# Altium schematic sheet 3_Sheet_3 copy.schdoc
size 302 x 215 mm; Name: A_A4; Symbol: A_A4; Device: A_A4; @Project Name: Quectel_EC200U_Board; REV: 1.1; Date: 11-07-24; Sheet: 1/1; Draw By: Anusha; Company: FervidSmart Solutions; Convert to PCB: yes; Add into BOM: yes; @Page No: 3; @Page Count: 3; @Schematic Name: Quectel_EC200U with BuckBoost Board; @Board Name: Quectel_EC200U with BuckBoost Board; @Update Date: 2025-06-23; @Create Time: 12:09:23; @Update Time: 12:51:10; @Page Name: Sheet_3 copy; @Create Date: 2025-06-19
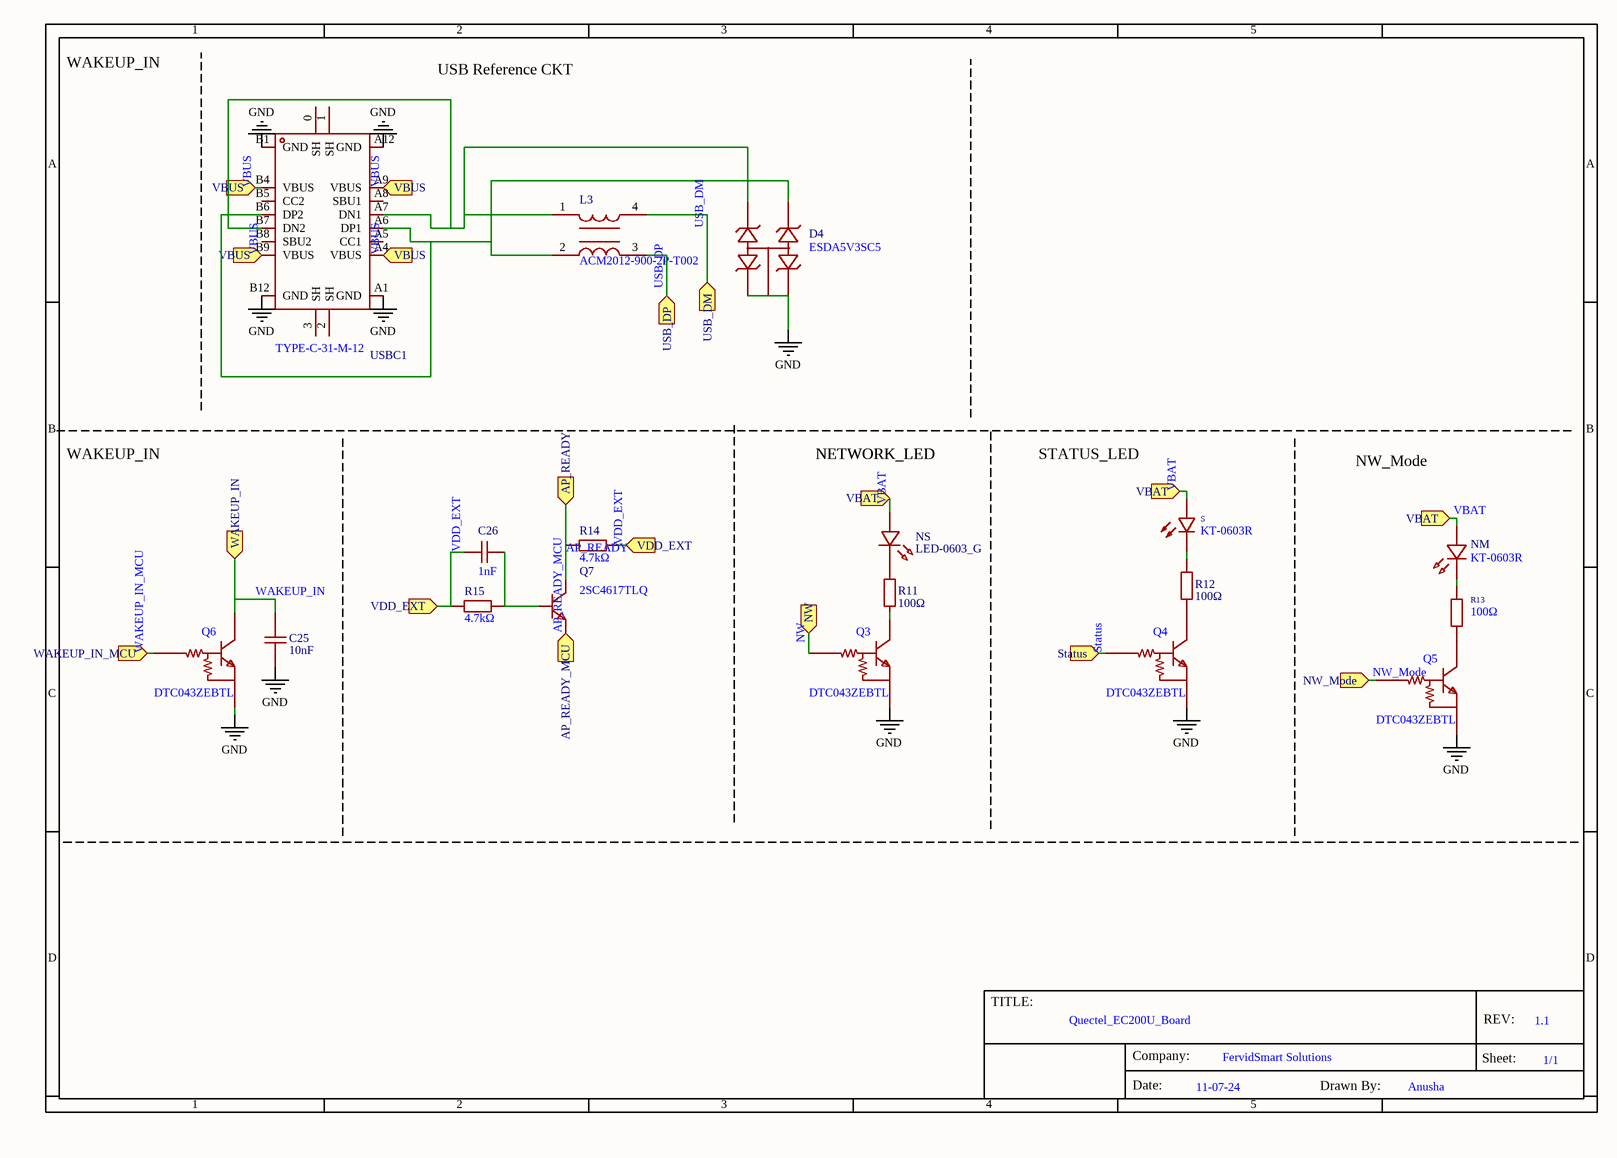
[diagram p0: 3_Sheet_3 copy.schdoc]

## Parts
C25  10nF  [C0603]
C26  1nF  [C0402]
D4  ESDA5V3SC5  [SOT-23-5_L3.0-W1.7-P0.95-LS2.8-BR]
L3  ACM2012-900-2P-T002  [IND-SMD_4P-L2.0-W1.2-TL]
NM  KT-0603R  [LED0603-RD]
NS  LED-0603_G  [LED0603_GREEN]
Q3  DTC043ZEBTL  [SOT-416_L1.6-W0.8-P1.00-LS1.6-BR]
Q4  DTC043ZEBTL  [SOT-416_L1.6-W0.8-P1.00-LS1.6-BR]
Q5  DTC043ZEBTL  [SOT-416_L1.6-W0.8-P1.00-LS1.6-BR]
Q6  DTC043ZEBTL  [SOT-416_L1.6-W0.8-P1.00-LS1.6-BR]
Q7  2SC4617TLQ  [SOT-416F_L1.6-W0.8-P1.00-LS1.6-TR]
R11  100Ω  [R0603]
R12  100Ω  [R0603]
R13  100Ω  [R0603]
R14  4.7kΩ  [R0402]
R15  4.7kΩ  [R0402]
S  KT-0603R  [LED0603-RD]
USBC1  TYPE-C-31-M-12  [USB-C_SMD-TYPE-C-31-M-12]

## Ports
AP_READY (in), AP_READY_MCU (in), NW (in), NW_Mode (in), Status (in), USB_DM (in), USB_DP (in), VBAT (in), VBUS (in), VDD_EXT (in), WAKEUP_IN (in), WAKEUP_IN_MCU (in)

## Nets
GND: C25.1 D4.1 D4.2 D4.3 Q3.2(E) Q4.2(E) Q5.2(E) Q6.2(E) USBC1.A1(GND) USBC1.A12(GND) USBC1.B1(GND) USBC1.B12(GND)
AP_READY: Q7.3(C) R14.1 ; port AP_READY
AP_READY_MCU: Q7.1(E) ; port AP_READY_MCU
NW: Q3.1(B) ; port NW
NW_Mode: Q5.1(B) ; port NW_Mode
Status: Q4.1(B) ; port Status
USB_DM: L3.4 ; port USB_DM
USB_DP: L3.3 ; port USB_DP
VBAT: NM.2(A) NS.1 S.2(+) ; port VBAT
VBUS: USBC1.A4(VBUS) USBC1.A9(VBUS) USBC1.B4(VBUS) USBC1.B9(VBUS) ; port VBUS
VDD_EXT: C26.1 R14.2 R15.1 ; port VDD_EXT
WAKEUP_IN: C25.2 Q6.3(C) ; port WAKEUP_IN
WAKEUP_IN_MCU: Q6.1(B) ; port WAKEUP_IN_MCU
NetC26_2: C26.2 Q7.2(B) R15.2
NetD4_4: D4.4 L3.2 USBC1.A6(DP1) USBC1.B6(DP2)
NetD4_5: D4.5 L3.1 USBC1.A7(DN1) USBC1.B7(DN2)
NetNM_1: NM.1(K) R13.2
NetNS_2: NS.2 R11.1
NetQ3_3: Q3.3(C) R11.2
NetQ4_3: Q4.3(C) R12.2
NetQ5_3: Q5.3(C) R13.1
NetR12_1: R12.1 S.1(-)

Not connected (* = marked no-connect by the designer): USBC1 0(SH) 1(SH) 2(SH) 3(SH) A5(CC1) A8(SBU1) B5(CC2) B8(SBU2)

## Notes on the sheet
- WAKEUP_IN
- USB Reference CKT
- NETWORK_LED
- STATUS_LED
- NW_Mode

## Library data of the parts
C25 = 0603B103K500NT: Manufacturer: FH(风华); Add into BOM: yes; Tolerance: ±10%; Voltage Rating: 50V; Temperature Coefficient: X7R; Check: true
C26 = 0402B102K500NT: Manufacturer: FH(风华); Symbol: CC0402KRX7R9BB102; Add into BOM: yes; Tolerance: ±10%; Check: true
D4 = ESDA5V3SC5: Manufacturer: ST(意法半导体); Add into BOM: yes; polarity: Unidirectional; Reverse Stand-Off Voltage (Vrwm): 3V; Maximum Clamping Voltage: 5.3V; Peak Pulse Power Dissipation (Ppp)@10/1000us: 500W; Number of Lines: Quad; Type: ESD; Check: true
L3 = ACM2012-900-2P-T002: Manufacturer: TDK; Add into BOM: yes; Number of Lines: 2; Withstanding Voltage: 50V; Current Rating: 400mA; Impedance @ Frequency: 90Ω@100MHz; DC Resistance (DCR): 190mΩ; Check: true
NM = F.0603.00139/P2-0603R1TS2-06T-002: Manufacturer: Hubei KENTO Elec; Add into BOM: yes; Emitted Color: Red; Forward Current: 5mA; Viewing Angle: 120°; Check: true
NS = 19-217/GHC-YR1S2/3T: Manufacturer: Hubei KENTO Elec; Manufacturer Part: KT-0603R; Convert to PCB: yes; Check: true
Q3-Q6 = DTC043ZEBTL: Manufacturer: ROHM(罗姆); Add into BOM: yes; Transistor Type: 1个NPN-预偏置; Collector-Emitter Breakdown Voltage (Vceo): 50V; Collector Current (Ic): 100mA; Power Dissipation (Pd): 150mW; DC Current Gain (hFE@Ic,Vce): 80@5mA,10V; Transition Frequency (fT): 250MHz; Collector-Emitter Saturation Voltage (VCE(sat)@Ic,Ib): 150mV@500uA,5mA; Check: true
Q7 = 2SC4617TLQ: Manufacturer: ROHM(罗姆); Add into BOM: yes; type: NPN; Pd - Power Dissipation: 200mW; DC Current Gain: 120@1mA,6V; Transition frequency(fT): 180MHz; Current - Collector Cutoff: 100nA; Vce Saturation(VCE(sat)): 400mV; Check: true
R11 R12 = RK73H1JTTD2201F: Manufacturer: UNI-ROYAL(Uniroyal Elec); Manufacturer Part: 0603WAF1000T5E; Symbol: 2.2kΩ; Resistance: 2.2K; Convert to PCB: yes; Check: true
R13 = 0603WAF2201T5E_C4190: Manufacturer: UNI-ROYAL(Uniroyal Elec); Manufacturer Part: 0603WAF1000T5E; Add into BOM: yes; Tolerance: ±1%; Temperature Coefficient: ±100ppm/℃; Check: true
R14 R15 = 0402WGF4701TCE: Manufacturer: UNI-ROYAL(厚声); Symbol: RC0402FR-074K7L; Add into BOM: yes; Tolerance: ±1%; Temperature Coefficient: ±100ppm/℃; Check: true
S = NCD0603C1: Manufacturer: Hubei KENTO Elec; Symbol: FC-D1608HGK-572C; Add into BOM: yes; Emitted Color: Green-yellow; Forward Voltage (VF): 1.6V~2.6V; Power Dissipation: 65mW; Forward Current: 5mA; Dominant Wavelength: 565nm~578nm; Lens Color: 无色透明透镜; Luminous Intensity: 5mcd~13mcd; Viewing Angle: 140°; Check: true
USBC1 = TYPE-C-31-M-12: Manufacturer: 韩国韩荣; Add into BOM: yes; Connector Type: Type-C; Gender: Female; Number of Contacts: 16P; Number of Ports: 1; Current Rating - Power (Max): 5A; Check: true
